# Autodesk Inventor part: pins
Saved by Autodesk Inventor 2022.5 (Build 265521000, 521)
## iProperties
Created: 2024-12
Part Number: pins
Material: Generic
Document SubType Name: Modeling
Designer: AdminForWorker
Density: 1 g/cm^3
Appearance: Default
Title: pins
Author: AdminForWorker
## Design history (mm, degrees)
feature "Body1"
feature "Body2"
feature "Body3"
feature "Body4"
feature "Body5"
feature "Body6"
feature "Body7"
feature "Body8"
feature "Body9"
feature "Body10"
feature "Body11"
feature "Body12"
feature "Body13"
feature "Body14"
feature "Body15"
feature "Body16"
feature "Body17"
feature "Body18"
feature "Body19"
feature "Body20"
feature "Body21"
feature "Body22"
feature "Body23"
feature "Body24"
feature "Body25"
feature "Body26"
feature "Body27"
feature "Body28"
feature "Body29"
feature "Body30"
feature "Body31"
feature "Body32"
feature "Body33"
feature "Body34"
feature "Body35"
feature "Body36"
feature "Body37"
feature "Body38"
feature "Body39"
feature "Body40"
body "Solid1"
body "Solid2"
body "Solid3"
body "Solid4"
body "Solid5"
body "Solid6"
body "Solid7"
body "Solid8"
body "Solid9"
body "Solid10"
body "Solid11"
body "Solid12"
body "Solid13"
body "Solid14"
body "Solid15"
body "Solid16"
body "Solid17"
body "Solid18"
body "Solid19"
body "Solid20"
body "Solid21"
body "Solid22"
body "Solid23"
body "Solid24"
body "Solid25"
body "Solid26"
body "Solid27"
body "Solid28"
body "Solid29"
body "Solid30"
body "Solid31"
body "Solid32"
body "Solid33"
body "Solid34"
body "Solid35"
body "Solid36"
body "Solid37"
body "Solid38"
body "Solid39"
body "Solid40"
